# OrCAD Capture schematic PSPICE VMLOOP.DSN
size B
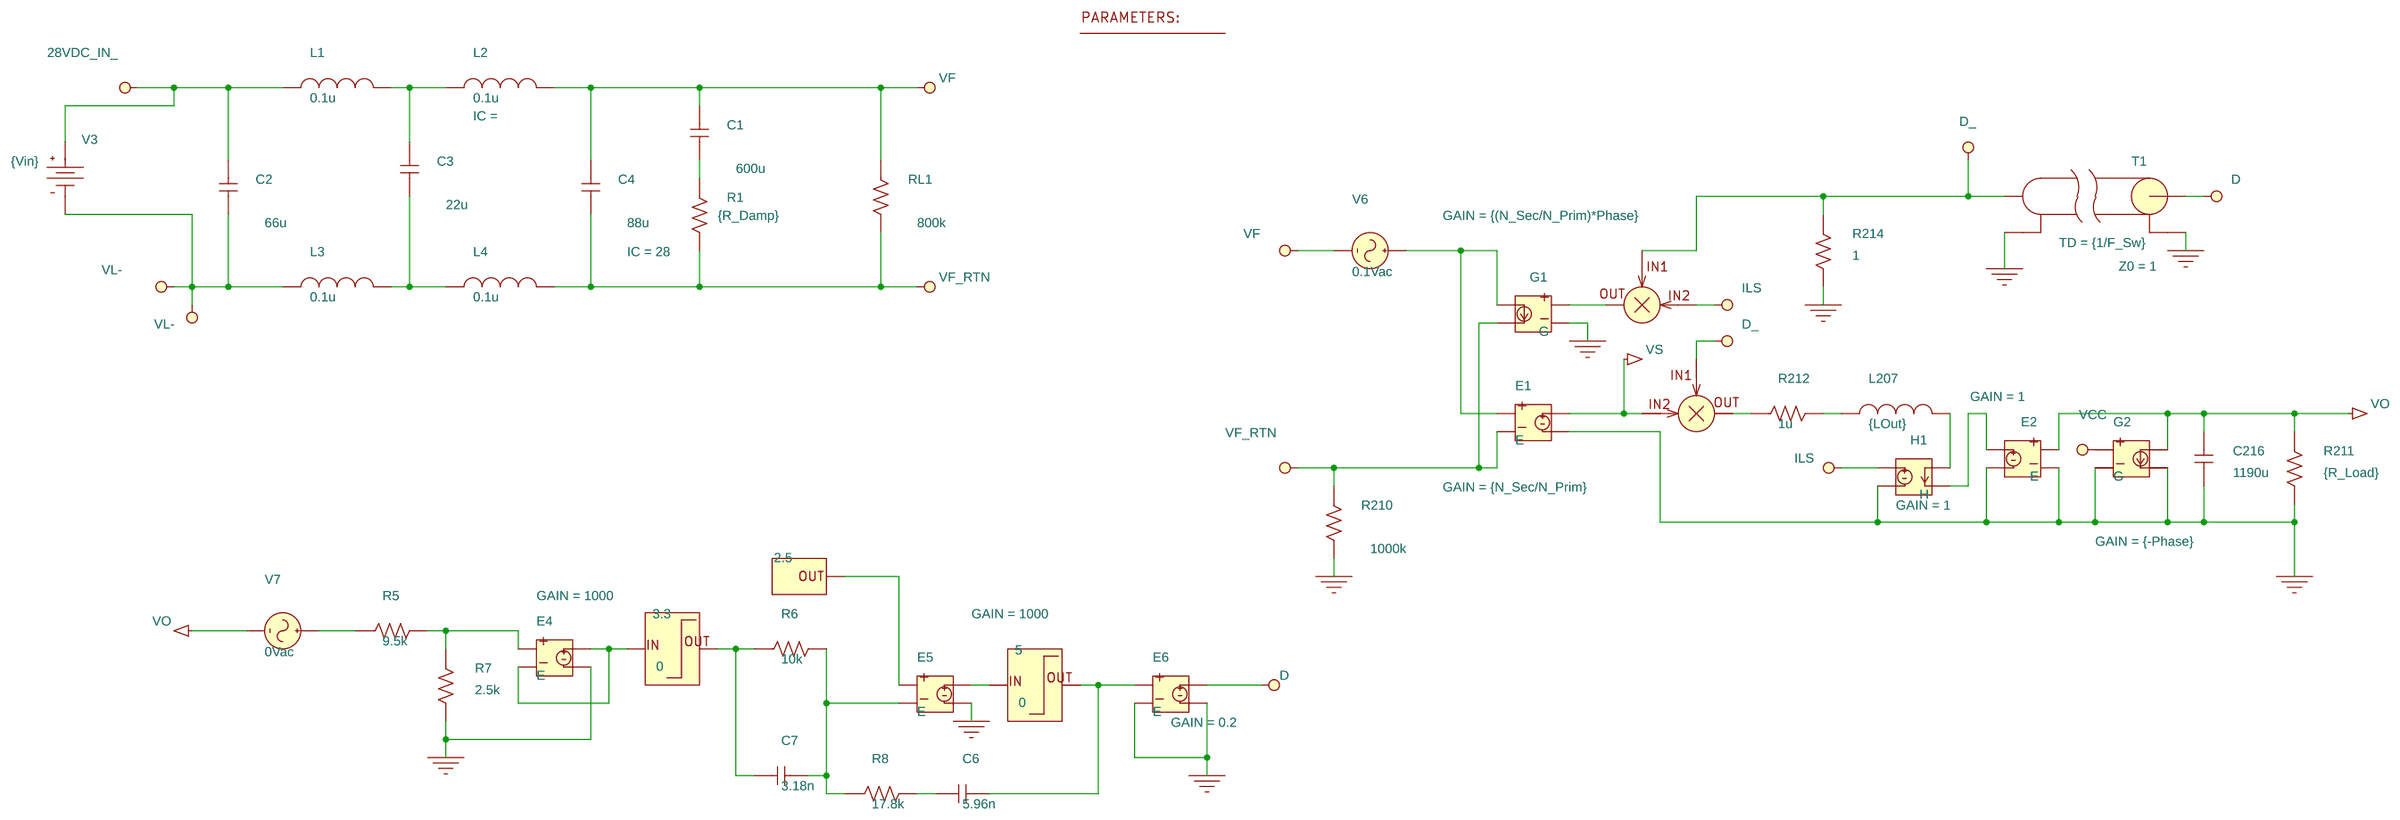
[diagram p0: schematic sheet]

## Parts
1  PARAM
C1  600u  [CK05]
C2  66u  [CK05]
C3  22u  [CK05]
C4  88u  [CK05]
C6  5.96n  [RAD/CK05]
C7  3.18n  [RAD/CK05]
C216  1190u  [CK05]
CONST3  2.5
E1  E
E2  E
E4  E
E5  E
E6  E
G1  G
G2  G
H1  H
L1  0.1u  [L2012C]
L2  0.1u  [L2012C]
L3  0.1u  [L2012C]
L4  0.1u  [L2012C]
L207  {LOut}  [L2012C]
LIMIT2  LIMIT
LIMIT3  LIMIT
MULT1  MULT
MULT4  MULT
R1  {R_Damp}  [RC05]
R5  9.5k  [AX/RC05]
R6  10k  [AX/RC05]
R7  2.5k  [AX/RC05]
R8  17.8k  [AX/RC05]
R210  1000k  [RC05]
R211  {R_Load}  [RC05]
R212  1u  [RC05]
R214  1  [RC05]
RL1  800k  [RC05]
T1  T
V3  VDC
V6  VAC
V7  VAC

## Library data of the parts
1 = PARAM: F_Sw: 300k; LOut: 4.4u; N_Prim: 4; N_Sec: 8; Phase: 2; R_Load: 0.192; Vin: 28
C1-C3 C6 C7 C216 = C
C4 = C: IC: 28
CONST3 = CONST
E1 = E: GAIN: {N_Sec/N_Prim}
E2 = E: GAIN: 1
E4 E5 = E: GAIN: 1000
E6 = E: GAIN: 0.2
G1 = G: GAIN: {(N_Sec/N_Prim)*Phase}
G2 = G: GAIN: {-Phase}
H1 = H: GAIN: 1
L1-L4 L207 = L_v2
LIMIT2 = LIMIT: HI: 3.3; LO: 0
LIMIT3 = LIMIT: HI: 5; LO: 0
MULT1 MULT4 = MULT
R1 R5-R8 R210-R212 R214 RL1 = R
T1 = T: TD: {1/F_Sw}; Z0: 1
V3 = VDC: DC: {Vin}
V6 = VAC: ACMAG: 0.1Vac
V7 = VAC: ACMAG: 0Vac

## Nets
28VDC_IN_: C2.1 L1.1 V3.0(+)
0: C216.2 E1.4 E2.2 E2.4 E4.4 E5.4 E6.2 E6.4 G1.2 G2.2 G2.4 H1.4 R7.2 R210.2 R211.2 R214.2 T1.2(A-) T1.4(B-)
D: E6.3 T1.1(A+)
D_: MULT1.1(IN1) MULT4.1(IN1) R214.1 T1.3(B+)
DC_IN_RTN: C2.2 L3.1 V3.1(-)
ILS: G2.1 H1.3 MULT4.3(IN2)
VF: C1.1 C4.1 L2.2 RL1.1 V6.2(-)
VF_RTN: C4.2 E1.2 G1.4 L4.2 R1.2 R210.1 RL1.2
Vo: C216.1 E2.1 G2.3 R211.1 V7.2(-)
Vs: E1.3 MULT1.3(IN2)
N29213: E1.1 G1.3 V6.1(+)
N29283: G1.1 MULT4.5(OUT)
N29439: H1.1 L207.2
N29449: E2.3 H1.2
N31522: MULT1.5(OUT) R212.1
N31526: L207.1 R212.2
N65813: CONST3.5(OUT) E5.1
N65879: E4.1 R5.2 R7.1
N65947: E4.2 E4.3 LIMIT2.1(IN)
N65961: C7.2 E5.2 R6.2 R8.1
N66077: E5.3 LIMIT3.1(IN)
N66083: C6.2 E6.1 LIMIT3.2(OUT)
N66221: C6.1 R8.2
N66517: C7.1 LIMIT2.2(OUT) R6.1
N67231: R5.1 V7.1(+)
N78892: C3.1 L1.2 L2.1
N78974: C1.2 R1.1
N79034: C3.2 L3.2 L4.1
